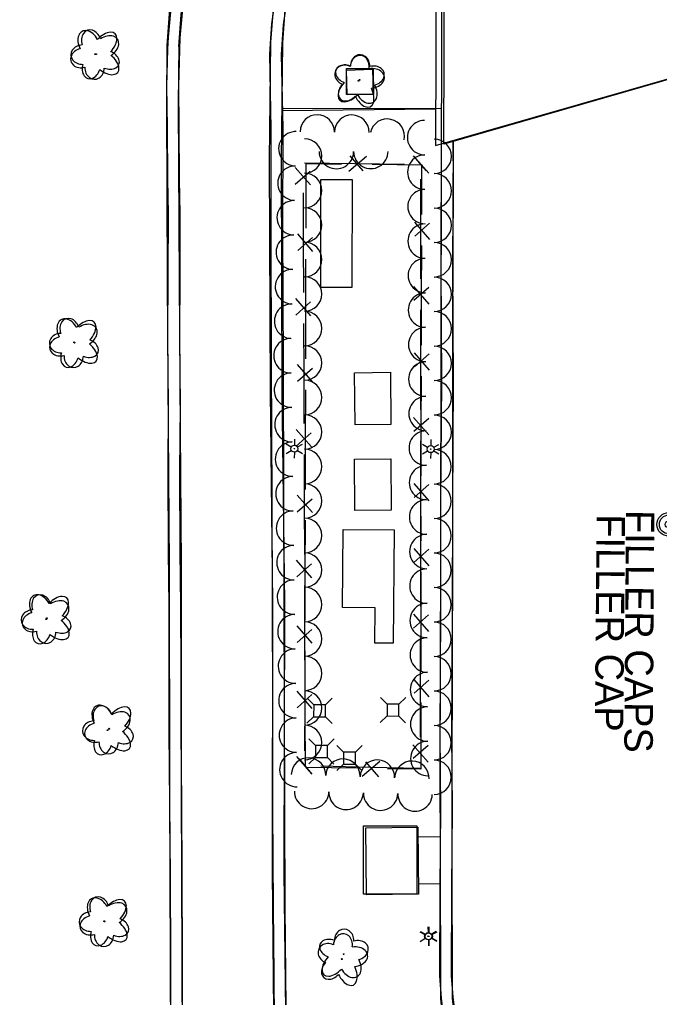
# Model space of a CAD drawing. Extents: x 588843 to 2552415, y 180129 to 269402.
# Drawn here: x 594213.6 to 594348.8, y 184744.9 to 184951.5 of the extents above; entities that cross this region are included whole.
import ezdxf

# ---------------------------------------------------------------- set-up
doc = ezdxf.new("R2010")
doc.units = 0
for name, color, linetype in [('Default', 7, 'Continuous'), ('E_AREA', 7, 'Continuous'), ('E_BLD', 7, 'Continuous'), ('E_BLD_HvyDash', 7, 'Continuous'), ('E_DWY', 7, 'Continuous'), ('E_FEN_P', 7, 'Continuous'), ('E_LAND_TreeLine_P', 7, 'Continuous'), ('E_LAND_Vegetation', 7, 'Continuous'), ('E_LTG', 7, 'Continuous'), ('E_MISCPROP', 7, 'Continuous'), ('E_MISCPROP_Text', 7, 'Continuous'), ('E_PATH_Sidewalk', 7, 'Continuous'), ('E_UTL_AG_Bold', 7, 'Continuous')]:
    doc.layers.add(name, color=color, linetype=linetype)

# ---------------------------------------------------------------- blocks, each defined once
blk = doc.blocks.new('DTRE')
at = {"layer": 'Default'}
blk.add_circle((-0.18, 0), 0.183, dxfattribs=at)
for centre, major_axis, ratio in [((-1.87, 5.32), (1.36, -4.98), 0.782863), ((-5.87, 0.15), (4.93, -0.12), 0.832022), ((4.06, 2.74), (-5.27, -2.93), 0.691916), ((-2.49, -5.24), (1.8, 4.86), 0.716896), ((3.54, -3.71), (-5.01, 4.58), 0.560249)]:
    blk.add_ellipse(centre, major_axis=major_axis, ratio=ratio, start_param=1.570796, end_param=4.712389, dxfattribs=at)
blk = doc.blocks.new('FILT_1')
at = {"layer": 'E_MISCPROP_Text'}
blk.add_text('FILLER CAPS', height=12, dxfattribs=at).set_placement((12, -3.99))
blk = doc.blocks.new('LPOL')
at = {"layer": 'Default'}
for p, q in [((-4, 0), (-1.5, 0)), ((-0.75, 1.3), (-2, 3.46)), ((0.75, 1.3), (2, 3.46)), ((1.5, 0), (4, 0)), ((-2, -3.46), (-0.75, -1.3)), ((2, -3.46), (0.75, -1.3))]:
    blk.add_line(p, q, dxfattribs=at)
for radius in [1.5, 1.5, 1.5, 0.125]:
    blk.add_circle((0, 0), radius, dxfattribs=at)
blk = doc.blocks.new('PED')
at = {"layer": 'Default'}
for p, q in [((-2.5, 2.5), (-5.33, 5.33)), ((2.5, 2.5), (5.33, 5.33)), ((-2.5, -2.5), (-5.33, -5.33)), ((2.5, -2.5), (5.33, -5.33))]:
    blk.add_line(p, q, dxfattribs=at)
blk.add_lwpolyline([(-2.5, -2.5), (2.5, -2.5), (2.5, 2.5), (-2.5, 2.5)], close=True, dxfattribs=at)
blk = doc.blocks.new('LPOL_4')
at = {"layer": 'E_LTG'}
for p, q in [((-13.1, 0), (-4.9, 0)), ((-2.5, 4.3), (-6.6, 11.4)), ((2.5, 4.3), (6.6, 11.4)), ((4.9, 0), (13.1, 0)), ((-6.6, -11.4), (-2.5, -4.3)), ((6.6, -11.4), (2.5, -4.3))]:
    blk.add_line(p, q, dxfattribs=at)
for radius in [4.92, 4.92, 4.92, 0.41]:
    blk.add_circle((0, 0), radius, dxfattribs=at)
blk = doc.blocks.new('FILO_1')
at = {"layer": 'E_MISCPROP'}
for radius in [16.4, 13.1, 4.92]:
    blk.add_circle((0, 0), radius, dxfattribs=at)
blk = doc.blocks.new('DTRE_4')
at = {"layer": 'E_LAND_Vegetation'}
blk.add_circle((-0.6, 0), 0.601, dxfattribs=at)
for centre, major_axis, ratio in [((-6.1, 17.5), (4.5, -16.3), 0.782863), ((-19.3, 0.5), (16.2, -0.4), 0.832022), ((13.3, 9), (-17.3, -9.6), 0.691916), ((-8.2, -17.2), (5.9, 15.9), 0.716896), ((11.6, -12.2), (-16.4, 15), 0.560249)]:
    blk.add_ellipse(centre, major_axis=major_axis, ratio=ratio, start_param=1.570796, end_param=4.712389, dxfattribs=at)
blk = doc.blocks.new('FILT_1_1')
at = {"layer": 'E_MISCPROP'}
blk.add_text('FILLER CAP', height=39.37, dxfattribs=at).set_placement((32.8, -19.7))

msp = doc.modelspace()

# ---------------------------------------------------------------- linework, layer by layer
at = {"layer": 'E_AREA'}
for points in [[(594277.27, 184894.88), (594277.32, 184917.73), (594283.88, 184917.72), (594283.83, 184894.87), (594277.27, 184894.88)], [(594281.89, 184827.27), (594282.04, 184843.78), (594292.81, 184843.68), (594292.58, 184819.75), (594288.73, 184819.79), (594288.8, 184827.21), (594281.89, 184827.27)]]:
    msp.add_lwpolyline(points, close=True, dxfattribs=at)
at = {"layer": 'E_BLD'}
for points in [[(594284.51, 184865.88), (594284.4, 184876.91), (594291.98, 184876.99), (594292.1, 184865.96), (594284.51, 184865.88)], [(594284.47, 184847.82), (594284.38, 184858.66), (594292.07, 184858.73), (594292.16, 184847.88), (594284.47, 184847.82)], [(594286.3, 184766.74), (594286.29, 184781.18), (594297.58, 184781.19), (594297.59, 184766.75), (594286.3, 184766.74)], [(594286.91, 184766.61), (594286.77, 184780.78), (594297.8, 184780.89), (594297.94, 184766.72)]]:
    msp.add_lwpolyline(points, close=True, dxfattribs=at)
at = {"layer": 'E_BLD_HvyDash'}
for points in [[(594403.05, 184993.52), (594301.64, 184963.67), (594301.5, 184924.9), (594403.68, 184954.23)], [(594303.44, 184964.27), (594404.56, 184993.57), (594403.99, 184954.19), (594303.25, 184925.21), (594303.44, 184964.27)]]:
    msp.add_lwpolyline(points, close=True, dxfattribs=at)
at = {"layer": 'E_DWY'}
for points in [[(594254.84, 185051.07), (594251.72, 185017.97), (594248.57, 184986.21), (594245.24, 184952.75), (594244.75, 184946.03)], [(594257.33, 185050.83), (594254.21, 185017.73), (594251.06, 184985.96), (594247.73, 184952.54), (594247.24, 184945.85)], [(594266.62, 184872.86), (594266.44, 184921.97), (594266.75, 184946.76), (594267.28, 184953.78), (594268, 184957.83), (594268.88, 184960.89)], [(594269.12, 184872.86), (594268.94, 184921.96), (594269.25, 184946.65), (594269.76, 184953.47), (594270.44, 184957.27), (594271.28, 184960.2)], [(594245.58, 184753.32), (594245.5, 184770.34), (594245.4, 184785.96), (594245.27, 184801.01), (594245.27, 184814.05), (594245.21, 184827.6), (594245.08, 184839.18), (594245, 184856.09), (594245.11, 184869.9), (594244.98, 184884.52), (594245.03, 184897.83), (594245.07, 184910.46), (594244.94, 184917.76), (594244.88, 184928.74), (594244.78, 184937.43), (594244.98, 184945.25), (594245.1, 184947.8), (594245.86, 184956.29)], [(594248.08, 184753.33), (594248, 184770.35), (594247.9, 184785.98), (594247.77, 184801.02), (594247.77, 184814.06), (594247.71, 184827.62), (594247.58, 184839.2), (594247.5, 184856.09), (594247.61, 184869.9), (594247.48, 184884.53), (594247.53, 184897.83), (594247.57, 184910.48), (594247.44, 184917.79), (594247.38, 184928.76), (594247.28, 184937.41), (594247.48, 184945.16), (594247.59, 184947.63), (594248.35, 184956.07)], [(594302.4, 184749.51), (594302.5, 184767.96), (594302.63, 184784.79), (594302.49, 184800.57), (594302.63, 184826.56), (594302.67, 184849.32), (594302.84, 184875.1), (594302.71, 184899.15), (594302.8, 184926.72), (594302.82, 184940.87), (594302.82, 184956.54)], [(594267.42, 184954.56), (594266.84, 184950.63), (594266.59, 184946.42), (594266.42, 184944.2), (594266.75, 184928.45), (594266.71, 184907.21), (594266.81, 184878.53), (594266.93, 184850.49), (594266.97, 184828.28), (594267.07, 184807.45), (594267.1, 184784.64), (594267.2, 184763.94), (594267.35, 184749.67)], [(594269.89, 184954.17), (594269.33, 184950.37), (594269.08, 184946.25), (594268.92, 184944.13), (594269.25, 184928.47), (594269.21, 184907.21), (594269.31, 184878.54), (594269.43, 184850.5), (594269.47, 184828.28), (594269.57, 184807.46), (594269.6, 184784.65), (594269.7, 184763.96), (594269.85, 184749.7)], [(594244.75, 184946.03), (594244.66, 184933.57), (594244.84, 184896.25), (594245.04, 184864.76)], [(594247.25, 184946.02), (594247.16, 184933.56), (594247.34, 184896.26), (594247.54, 184864.77)], [(594304.9, 184749.49), (594305, 184767.94), (594305.13, 184784.79), (594304.99, 184800.57), (594305.13, 184826.55), (594305.17, 184849.31), (594305.34, 184875.1), (594305.21, 184899.15), (594305.3, 184925.8)], [(594305.21, 184925.96), (594305.23, 184917.31), (594305.13, 184886.2), (594305.08, 184838.1)], [(594302.71, 184925.25), (594302.73, 184917.31), (594302.63, 184886.21), (594302.58, 184838.1)], [(594267.36, 184741.98), (594267.06, 184771.36), (594267.17, 184828.26), (594266.62, 184872.83)], [(594269.86, 184742), (594269.56, 184771.37), (594269.67, 184828.27), (594269.12, 184872.86)], [(594245.04, 184864.76), (594245.25, 184836.13), (594245.31, 184788.4), (594245.49, 184735)], [(594247.54, 184864.77), (594247.75, 184836.14), (594247.81, 184788.4), (594247.99, 184735.01)], [(594302.58, 184838.1), (594302.46, 184791.86), (594302.49, 184775.87)], [(594305.08, 184838.09), (594304.96, 184791.85), (594304.99, 184775.88)], [(594302.49, 184775.87), (594302.56, 184744.62), (594303.02, 184740.5), (594303.65, 184737.35), (594305.15, 184732.93), (594314.39, 184709.4)], [(594304.99, 184775.88), (594305.06, 184744.77), (594305.49, 184740.89), (594306.07, 184738), (594307.5, 184733.79), (594316.72, 184710.31)], [(594260.66, 184632.53), (594257.62, 184638.15), (594255.26, 184643.55), (594251.87, 184652.74), (594249.6, 184660.33), (594247.48, 184671.23), (594246.51, 184679.38), (594246.09, 184686.11), (594245.84, 184699.26), (594245.71, 184715.35), (594245.64, 184729.43), (594245.58, 184753.32)], [(594262.8, 184633.83), (594259.87, 184639.25), (594257.58, 184644.48), (594254.24, 184653.53), (594252.03, 184660.93), (594249.96, 184671.62), (594249, 184679.6), (594248.59, 184686.21), (594248.34, 184699.29), (594248.21, 184715.37), (594248.14, 184729.44), (594248.08, 184753.33)], [(594267.35, 184749.67), (594267.52, 184729.61), (594267.68, 184715.78), (594267.49, 184703.22), (594267.72, 184695.2), (594268.41, 184687.9), (594269.42, 184682.03), (594271, 184675.34), (594272.92, 184669.45), (594275.27, 184663.44), (594278.56, 184656.7), (594282.17, 184650.36), (594286.18, 184644.26), (594290.4, 184638.7), (594293.87, 184634.76), (594298.84, 184630.22)], [(594269.85, 184749.7), (594270.02, 184729.63), (594270.18, 184715.78), (594269.99, 184703.24), (594270.21, 184695.36), (594270.89, 184688.23), (594271.87, 184682.53), (594273.41, 184676.02), (594275.28, 184670.29), (594277.56, 184664.45), (594280.77, 184657.86), (594284.3, 184651.67), (594288.22, 184645.7), (594292.33, 184640.29), (594295.66, 184636.52), (594300.48, 184632.11)], [(594343.9, 184633.81), (594338.05, 184649.29), (594331.94, 184665.09), (594323.86, 184686.17), (594314.25, 184710.14), (594309.05, 184723.4), (594305.25, 184733.4), (594303.77, 184738.32), (594303.18, 184741.38), (594302.77, 184744.75), (594302.4, 184749.51)], [(594346.24, 184634.7), (594340.39, 184650.18), (594334.28, 184665.98), (594326.19, 184687.08), (594316.57, 184711.06), (594311.38, 184724.3), (594307.62, 184734.21), (594306.2, 184738.92), (594305.65, 184741.77), (594305.26, 184744.97), (594304.9, 184749.49)]]:
    msp.add_lwpolyline(points, dxfattribs=at)
at = {"layer": 'E_FEN_P'}
for p, q in [((594283.23, 184919.5), (594286.93, 184922.66)), ((594283.43, 184922.7), (594286.16, 184919.54)), ((594296.78, 184922.69), (594299.51, 184919.53)), ((594296.89, 184922.73), (594300.09, 184919.05)), ((594275.09, 184916.56), (594271.87, 184920.23)), ((594271.88, 184916.72), (594275.01, 184919.5)), ((594297.08, 184908.69), (594300.26, 184905.01)), ((594300.27, 184908.51), (594297.14, 184905.76)), ((594275.62, 184902.53), (594272.43, 184906.21)), ((594272.43, 184902.71), (594275.56, 184905.46)), ((594296.9, 184895.08), (594300.1, 184891.4)), ((594300.1, 184894.91), (594296.96, 184892.14)), ((594275.18, 184888.91), (594271.97, 184892.58)), ((594271.98, 184889.07), (594275.11, 184891.85)), ((594297, 184881.09), (594300.19, 184877.41)), ((594300.2, 184880.91), (594297.06, 184878.16)), ((594275.57, 184874.93), (594272.38, 184878.61)), ((594272.37, 184875.11), (594275.51, 184877.86)), ((594296.9, 184867.42), (594300.11, 184863.75)), ((594300.1, 184867.26), (594296.97, 184864.49)), ((594275.28, 184861.26), (594272.07, 184864.92)), ((594272.08, 184861.41), (594275.21, 184864.19)), ((594296.92, 184853.49), (594300.11, 184849.81)), ((594300.12, 184853.32), (594296.98, 184850.56)), ((594272.31, 184847.51), (594275.45, 184850.27)), ((594275.51, 184847.34), (594272.32, 184851.01)), ((594296.91, 184839.77), (594300.11, 184836.09)), ((594300.11, 184839.6), (594296.97, 184836.84)), ((594275.38, 184833.6), (594272.16, 184837.27)), ((594272.18, 184833.76), (594275.3, 184836.54)), ((594296.84, 184825.89), (594300.03, 184822.21)), ((594300.04, 184825.72), (594296.9, 184822.96)), ((594272.26, 184819.91), (594275.39, 184822.67)), ((594275.46, 184819.74), (594272.27, 184823.41)), ((594296.91, 184812.12), (594300.12, 184808.44)), ((594300.12, 184811.95), (594296.98, 184809.18)), ((594275.48, 184805.95), (594272.26, 184809.62)), ((594272.27, 184806.11), (594275.4, 184808.89)), ((594296.76, 184798.3), (594299.95, 184794.62)), ((594299.96, 184798.12), (594296.82, 184795.37)), ((594275.4, 184792.14), (594272.21, 184795.82)), ((594275.45, 184792.11), (594272.76, 184795.31)), ((594289.73, 184794.74), (594286.01, 184791.59)), ((594289.52, 184791.54), (594286.8, 184794.72))]:
    msp.add_line(p, q, dxfattribs=at)
for points in [[(594273.85, 184921.21), (594284.41, 184921.1)], [(594274.18, 184917.97), (594274.18, 184921.07), (594281.62, 184920.99)], [(594284.41, 184921.1), (594294.97, 184920.99)], [(594288.15, 184920.93), (594298.68, 184920.82)], [(594298.59, 184920.84), (594298.56, 184910.31)], [(594274.16, 184907.44), (594274.18, 184917.97)], [(594298.37, 184917.82), (594298.37, 184907.26)], [(594273.65, 184904.37), (594273.61, 184914.93)], [(594298.37, 184907.26), (594298.38, 184896.7)], [(594273.69, 184893.82), (594273.65, 184904.37)], [(594298.54, 184903.78), (594298.51, 184893.25)], [(594274.12, 184890.38), (594274.14, 184900.91)], [(594298.51, 184893.25), (594298.48, 184882.71)], [(594274.1, 184879.84), (594274.12, 184890.38)], [(594298.38, 184890.17), (594298.38, 184879.61)], [(594273.75, 184876.72), (594273.71, 184887.28)], [(594298.38, 184879.61), (594298.38, 184869.05)], [(594273.79, 184866.16), (594273.75, 184876.72)], [(594298.46, 184876.18), (594298.43, 184865.65)], [(594274.07, 184862.78), (594274.09, 184873.32)], [(594298.43, 184865.65), (594298.4, 184855.11)], [(594274.04, 184852.24), (594274.07, 184862.78)], [(594298.38, 184862.51), (594298.38, 184851.95)], [(594273.85, 184849.07), (594273.81, 184859.63)], [(594298.38, 184851.95), (594298.39, 184841.4)], [(594273.88, 184838.51), (594273.85, 184849.07)], [(594298.38, 184848.59), (594298.35, 184838.05)], [(594274.01, 184835.18), (594274.03, 184845.72)], [(594298.35, 184838.05), (594298.32, 184827.51)], [(594273.99, 184824.64), (594274.01, 184835.18)], [(594298.39, 184834.86), (594298.39, 184824.3)], [(594273.94, 184821.42), (594273.91, 184831.97)], [(594298.39, 184824.3), (594298.39, 184813.74)], [(594273.98, 184810.86), (594273.94, 184821.42)], [(594298.3, 184820.99), (594298.27, 184810.45)], [(594273.95, 184807.58), (594273.98, 184818.12)], [(594298.27, 184810.45), (594298.24, 184799.91)], [(594273.93, 184797.04), (594273.95, 184807.58)], [(594298.39, 184807.21), (594298.39, 184796.65)], [(594274.04, 184793.76), (594274, 184804.32)], [(594298.39, 184796.65), (594298.4, 184793.15), (594291.34, 184793.24)], [(594287.81, 184793.53), (594277.28, 184793.79)], [(594284.8, 184793.33), (594274.25, 184793.47)], [(594298.23, 184793.39), (594298.22, 184793.27), (594287.81, 184793.53)]]:
    msp.add_lwpolyline(points, dxfattribs=at)
at = {"layer": 'E_LAND_TreeLine_P'}
for centre, start, end in [((594276.54, 184927.77), 359.5725, 179.5725), ((594283.83, 184927.71), 359.5725, 179.5725), ((594291.32, 184926.87), 347.5702, 167.5702), ((594299.21, 184926.57), 90.3034, 270.3034), ((594272.01, 184924.21), 88.574, 268.574), ((594273.85, 184922.68), 269.9957, 89.9957), ((594301.24, 184922.62), 269.9874, 89.9874), ((594280.57, 184923.62), 180.2832, 0.2832), ((594287.86, 184923.65), 180.2832, 0.2832), ((594299.25, 184919.28), 90.3034, 270.3034), ((594271.83, 184916.93), 88.574, 268.574), ((594273.85, 184915.4), 269.9957, 89.9957), ((594301.24, 184915.33), 269.9874, 89.9874), ((594299.29, 184912), 90.3034, 270.3034), ((594271.65, 184909.64), 88.574, 268.574), ((594273.85, 184908.11), 269.9957, 89.9957), ((594301.24, 184908.04), 269.9874, 89.9874), ((594299.33, 184904.71), 90.3034, 270.3034), ((594271.47, 184902.36), 88.574, 268.574), ((594273.85, 184900.82), 269.9957, 89.9957), ((594301.23, 184900.76), 269.9874, 89.9874), ((594299.36, 184897.42), 90.3034, 270.3034), ((594271.29, 184895.07), 88.574, 268.574), ((594273.85, 184893.53), 269.9957, 89.9957), ((594301.23, 184893.47), 269.9874, 89.9874), ((594299.4, 184890.13), 90.3034, 270.3034), ((594271.1, 184887.79), 88.574, 268.574), ((594273.85, 184886.25), 269.9957, 89.9957), ((594301.23, 184886.18), 269.9874, 89.9874), ((594299.44, 184882.85), 90.3034, 270.3034), ((594270.97, 184880.5), 90.8414, 270.8414), ((594273.85, 184878.96), 269.9957, 89.9957), ((594301.23, 184878.89), 269.9874, 89.9874), ((594299.48, 184875.56), 90.3034, 270.3034), ((594271.07, 184873.21), 90.8414, 270.8414), ((594273.85, 184871.67), 269.9957, 89.9957), ((594301.23, 184871.61), 269.9874, 89.9874), ((594299.52, 184868.27), 90.3034, 270.3034), ((594271.18, 184865.93), 90.8414, 270.8414), ((594273.85, 184864.38), 269.9957, 89.9957), ((594301.23, 184864.32), 269.9874, 89.9874), ((594299.56, 184860.98), 90.3034, 270.3034), ((594271.29, 184858.64), 90.8414, 270.8414), ((594273.85, 184857.09), 269.9957, 89.9957), ((594301.22, 184857.03), 269.9874, 89.9874), ((594299.6, 184853.7), 90.3034, 270.3034), ((594271.39, 184851.35), 90.8414, 270.8414), ((594273.85, 184849.81), 269.9957, 89.9957), ((594301.22, 184849.74), 269.9874, 89.9874), ((594299.63, 184846.41), 90.3034, 270.3034), ((594271.5, 184844.07), 90.8414, 270.8414), ((594273.85, 184842.52), 269.9957, 89.9957), ((594301.22, 184842.46), 269.9874, 89.9874), ((594299.67, 184839.12), 90.3034, 270.3034), ((594271.61, 184836.78), 90.8414, 270.8414), ((594273.85, 184835.23), 269.9957, 89.9957), ((594301.22, 184835.17), 269.9874, 89.9874), ((594299.71, 184831.83), 90.3034, 270.3034), ((594271.71, 184829.49), 90.7884, 270.7884), ((594273.85, 184827.94), 269.9957, 89.9957), ((594301.22, 184827.88), 269.9874, 89.9874), ((594299.75, 184824.55), 90.3034, 270.3034), ((594271.81, 184822.21), 90.7884, 270.7884), ((594273.85, 184820.66), 269.9957, 89.9957), ((594301.22, 184820.59), 269.9874, 89.9874), ((594299.79, 184817.26), 90.3034, 270.3034), ((594271.91, 184814.92), 90.7884, 270.7884), ((594273.84, 184813.37), 269.9957, 89.9957), ((594301.22, 184813.31), 269.9874, 89.9874), ((594299.83, 184809.97), 90.3034, 270.3034), ((594272.02, 184807.63), 90.7884, 270.7884), ((594273.84, 184806.08), 269.9957, 89.9957), ((594301.21, 184806.02), 269.9874, 89.9874), ((594299.87, 184802.68), 90.3034, 270.3034), ((594272.12, 184800.34), 90.7884, 270.7884), ((594273.84, 184798.79), 269.9957, 89.9957), ((594301.21, 184798.73), 269.9874, 89.9874), ((594299.9, 184795.4), 90.3034, 270.3034), ((594272.22, 184793.06), 90.7884, 270.7884), ((594274.67, 184791.91), 358.1983, 178.1983), ((594281.95, 184791.68), 358.1983, 178.1983), ((594289.23, 184791.45), 358.1983, 178.1983), ((594296.52, 184791.22), 358.1983, 178.1983), ((594301.21, 184791.44), 269.9874, 89.9874), ((594275.35, 184788.44), 178.5658, 358.5658), ((594282.63, 184788.26), 178.5658, 358.5658), ((594289.92, 184788.08), 178.5658, 358.5658), ((594297.2, 184787.89), 178.5658, 358.5658)]:
    msp.add_arc(centre, 3.64, start, end, dxfattribs=at)
at = {"layer": 'E_PATH_Sidewalk'}
for points in [[(594282.84, 184935.59), (594282.68, 184940.85), (594288.19, 184941.02), (594288.35, 184935.76)], [(594288.39, 184935.71), (594282.74, 184935.69), (594282.73, 184941.15), (594288.37, 184941.17), (594288.39, 184935.71)]]:
    msp.add_lwpolyline(points, close=True, dxfattribs=at)
for points in [[(594269.07, 184932.32), (594301.53, 184932.68)], [(594269.16, 184932.72), (594302.81, 184932.78)], [(594302.48, 184778.82), (594297.82, 184778.8)], [(594302.51, 184768.89), (594297.92, 184768.94)]]:
    msp.add_lwpolyline(points, dxfattribs=at)

# ---------------------------------------------------------------- block references
at = {"layer": 'E_LAND_Vegetation'}
for name, p, xscale, yscale, rotation in [('DTRE', (594229.61, 184944.28), 0.49999999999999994, 0.5, 89.10482727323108), ('DTRE_4', (594229.88, 184944.2), 0.15240030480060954, 0.15240030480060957, 3.4338469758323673), ('DTRE_4', (594285.33, 184938.55), 0.1524003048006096, 0.15240030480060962, -22.11088937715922), ('DTRE', (594285.49, 184938.69), 0.4999999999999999, 0.49999999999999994, -90.39935623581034), ('DTRE_4', (594225.33, 184883.25), 0.15240030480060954, 0.15240030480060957, 3.4338469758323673), ('DTRE', (594225.19, 184883.39), 0.49999999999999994, 0.5, 89.10482727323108), ('DTRE_4', (594219.37, 184824.85), 0.15240030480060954, 0.15240030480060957, 3.4338469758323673), ('DTRE', (594219.39, 184825.12), 0.49999999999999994, 0.5, 89.10482727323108), ('DTRE_4', (594232.32, 184801.39), 0.15240030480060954, 0.15240030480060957, 3.4338469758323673), ('DTRE', (594232.58, 184801.78), 0.49999999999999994, 0.5, 89.10482727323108), ('DTRE_4', (594231.62, 184761.04), 0.15240030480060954, 0.15240030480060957, 3.4338469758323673), ('DTRE', (594231.6, 184761.08), 0.49999999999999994, 0.5, 89.10482727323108), ('DTRE_4', (594281.79, 184753), 0.1524003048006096, 0.15240030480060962, -22.11088937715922), ('DTRE', (594282.11, 184753.97), 0.4999999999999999, 0.49999999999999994, -90.39935623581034)]:
    msp.add_blockref(name, p, dxfattribs=dict(at, xscale=xscale, yscale=yscale, rotation=rotation))
at = {"layer": 'E_LTG'}
for name, p, xscale, yscale, rotation in [('LPOL', (594271.7, 184860.85), 0.4999999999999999, 0.49999999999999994, -90.39935623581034), ('LPOL', (594300.5, 184860.77), 0.4999999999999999, 0.49999999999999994, -90.39935623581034), ('LPOL_4', (594299.97, 184757.85), 0.15240030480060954, 0.15240030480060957, -87.10404271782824), ('LPOL', (594300.1, 184757.83), 0.4999999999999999, 0.49999999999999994, -90.39935623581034)]:
    msp.add_blockref(name, p, dxfattribs=dict(at, xscale=xscale, yscale=yscale, rotation=rotation))
at = {"layer": 'E_MISCPROP'}
for name, p, xscale, yscale, rotation in [('FILO_1', (594350.81, 184844.86), 0.15240030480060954, 0.15240030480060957, 3.4338469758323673), ('FILT_1_1', (594338.6, 184851.99), 0.1524003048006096, 0.15240030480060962, -90.46527130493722)]:
    msp.add_blockref(name, p, dxfattribs=dict(at, xscale=xscale, yscale=yscale, rotation=rotation))
at = {"layer": 'E_MISCPROP_Text', "xscale": 0.4999999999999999, "yscale": 0.49999999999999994, "rotation": -90.39935623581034}
msp.add_blockref('FILT_1', (594343.8, 184853.9), dxfattribs=at)
at = {"layer": 'E_UTL_AG_Bold', "xscale": 0.4999999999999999, "yscale": 0.49999999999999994, "rotation": -90.39935623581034}
for p in [(594277.03, 184805.48), (594292.53, 184805.63), (594277.42, 184796.89), (594283.34, 184795.48)]:
    msp.add_blockref('PED', p, dxfattribs=at)

doc.saveas('drawing.dxf')
